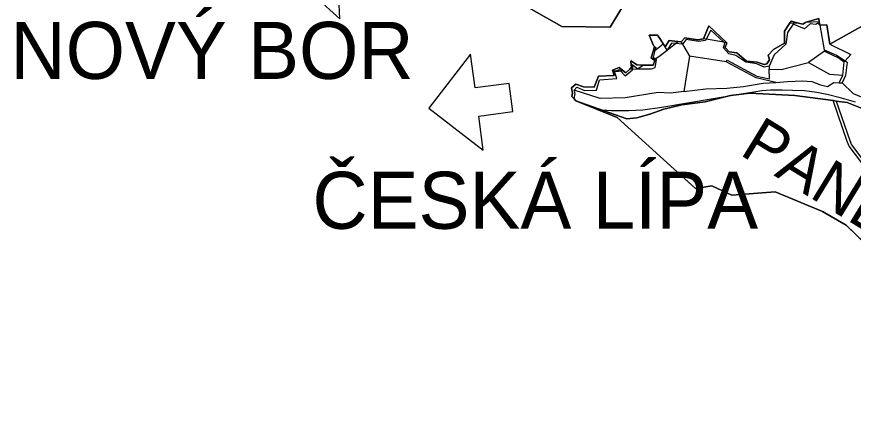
# Model space of a CAD drawing. Extents: x -706771 to -698463, y -971709 to -967107.
# Drawn here: x -706403 to -705305, y -970193 to -969665 of the extents above; entities that cross this region are included whole.
import ezdxf

# ---------------------------------------------------------------- set-up
doc = ezdxf.new("R2010")
doc.units = 0
for name, color, linetype in [('_KRAJINNY CELEK', 7, 'Continuous'), ('_KRAJINNY OKRSEK', 7, 'Continuous'), ('_KRAJINNY OKRSEK_popis', 7, 'Continuous'), ('Dráha_osa koleje', 7, 'Continuous'), ('Hranice katastralnich uzemi', 7, 'Continuous'), ('Hranice řešeného území', 7, 'Continuous'), ('KN_Hranice_parcel', 7, 'Continuous'), ('Komunikace popis smery a sipky', 7, 'Continuous'), ('Trasy cykloturistické N', 7, 'Continuous'), ('Typ krajiny běžné 5M2', 7, 'Continuous')]:
    doc.layers.add(name, color=color, linetype=linetype)

msp = doc.modelspace()

# ---------------------------------------------------------------- linework, layer by layer
at = {"layer": '_KRAJINNY CELEK'}
for points in [[(-705740.9, -969647.9), (-705687.4, -969678.2), (-705623.8, -969679), (-705593.1, -969627.6)], [(-705276.5, -969668.4), (-705335.3, -969701.6), (-705339.1, -969675.9), (-705348.7, -969676.4), (-705349.2, -969672.2), (-705349.9, -969667.5), (-705365, -969671.9), (-705367.1, -969673.1), (-705370.6, -969675.1), (-705376.6, -969673.6), (-705386.3, -969671.1), (-705388.2, -969674.3), (-705394.7, -969684.5), (-705394.9, -969700.3), (-705409.2, -969708.6), (-705416.3, -969715.9), (-705414.7, -969722.2), (-705418.1, -969727.2), (-705421.6, -969728.2), (-705430.7, -969725), (-705445, -969723.6), (-705457.7, -969712.8), (-705467.4, -969711.6), (-705473, -969705.6), (-705470.6, -969699.7), (-705494.1, -969677.1), (-705501.1, -969694.4), (-705508.8, -969695.8), (-705525.9, -969693.1), (-705530.6, -969698.3), (-705534.8, -969697.9), (-705546.5, -969696.7), (-705551.8, -969704.9), (-705554.2, -969701.1), (-705557.8, -969695.5), (-705561.6, -969689.6), (-705572.6, -969689.4), (-705566.9, -969703.3), (-705565.7, -969704.4), (-705567.4, -969711), (-705570, -969719.3), (-705566.7, -969722), (-705565.3, -969723.1), (-705567.2, -969729), (-705580.4, -969729.2), (-705588.9, -969728.7), (-705594.5, -969724.8), (-705596.7, -969723.2), (-705596.5, -969725.3), (-705595.9, -969731.7), (-705597.9, -969734.3), (-705603.4, -969739), (-705607.3, -969735.9), (-705612.2, -969732.1), (-705620.8, -969735.4), (-705620.2, -969737.1), (-705618.4, -969742.8), (-705639.1, -969743.7), (-705644.9, -969757.8), (-705658.9, -969757.7), (-705669.1, -969753.8), (-705674.6, -969758.8), (-705673.2, -969766), (-705674.2, -969770.1), (-705671.3, -969773.3), (-705669.1, -969775.8), (-705614.7, -969798), (-705511.8, -969891.3), (-705490.4, -969887.9), (-705463.9, -969899.8), (-705407.2, -969895.8), (-705344.8, -969921.3), (-705313.7, -969939.2), (-705269.7, -969982.5)]]:
    msp.add_lwpolyline(points, dxfattribs=at)
at = {"layer": '_KRAJINNY OKRSEK'}
for p, q in [((-705330.9, -969775.7), (-705381.4, -969769.1)), ((-705669.1, -969775.8), (-705614.7, -969798)), ((-705529.9, -969781.4), (-705553.4, -969786.8)), ((-705327.1, -969776.2), (-705330.9, -969775.7)), ((-705553.4, -969786.8), (-705571.6, -969793.4)), ((-705614.7, -969798), (-705511.8, -969891.3)), ((-705511.8, -969891.3), (-705490.4, -969887.9)), ((-705490.4, -969887.9), (-705463.9, -969899.8)), ((-705463.9, -969899.8), (-705407.2, -969895.8))]:
    msp.add_line(p, q, dxfattribs=at)
for points in [[(-705740.9, -969647.9), (-705687.4, -969678.2), (-705623.8, -969679), (-705593.1, -969627.6)], [(-705276.5, -969668.4), (-705335.3, -969701.6), (-705339.1, -969675.9), (-705348.7, -969676.4), (-705349.2, -969672.2), (-705349.9, -969667.5), (-705365, -969671.9), (-705367.1, -969673.1), (-705370.6, -969675.1), (-705376.6, -969673.6), (-705386.3, -969671.1), (-705388.2, -969674.3), (-705394.7, -969684.5), (-705394.9, -969700.3), (-705409.2, -969708.6), (-705416.3, -969715.9), (-705414.7, -969722.2), (-705418.1, -969727.2), (-705421.6, -969728.2), (-705430.7, -969725), (-705445, -969723.6), (-705457.7, -969712.8), (-705467.4, -969711.6), (-705473, -969705.6), (-705470.6, -969699.7), (-705494.1, -969677.1), (-705501.1, -969694.4), (-705508.8, -969695.8), (-705525.9, -969693.1), (-705530.6, -969698.3), (-705534.8, -969697.9), (-705546.5, -969696.7), (-705551.8, -969704.9), (-705554.2, -969701.1), (-705557.8, -969695.5), (-705561.6, -969689.6), (-705572.6, -969689.4), (-705566.9, -969703.3), (-705565.7, -969704.4), (-705567.4, -969711), (-705570, -969719.3), (-705566.7, -969722), (-705565.3, -969723.1), (-705567.2, -969729), (-705580.4, -969729.2), (-705588.9, -969728.7), (-705594.5, -969724.8), (-705596.7, -969723.2), (-705596.5, -969725.3), (-705595.9, -969731.7), (-705597.9, -969734.3), (-705603.4, -969739), (-705607.3, -969735.9), (-705612.2, -969732.1), (-705620.8, -969735.4), (-705620.2, -969737.1), (-705618.4, -969742.8), (-705639.1, -969743.7), (-705644.9, -969757.8), (-705658.9, -969757.7), (-705669.1, -969753.8), (-705674.6, -969758.8), (-705673.2, -969766), (-705674.2, -969770.1), (-705671.3, -969773.3), (-705669.1, -969775.8)], [(-705669.1, -969775.8), (-705601.9, -969799.5), (-705589, -969798.2), (-705571.6, -969793.4), (-705553.4, -969786.8), (-705529.9, -969781.4), (-705499, -969777.4), (-705465.6, -969768.8), (-705440.5, -969765.8), (-705381.4, -969769.1), (-705330.9, -969775.7), (-705327.1, -969776.2), (-705312.8, -969778.1), (-705282, -969790.5), (-705271.3, -969796.9), (-705242.7, -969817), (-705218.4, -969838.2), (-705184.7, -969864.5), (-705155.9, -969891.9), (-705141.2, -969879.4), (-705133, -969887.2), (-705116.4, -969899)], [(-705381.4, -969769.1), (-705440.5, -969765.8), (-705465.6, -969768.8), (-705499, -969777.4), (-705529.9, -969781.4)], [(-705571.6, -969793.4), (-705589, -969798.2), (-705601.9, -969799.5), (-705669.1, -969775.8)], [(-705282, -969790.5), (-705312.8, -969778.1), (-705327.1, -969776.2)], [(-705407.2, -969895.8), (-705344.8, -969921.3), (-705313.7, -969939.2), (-705269.7, -969982.5), (-705267.9, -969984.3)]]:
    msp.add_lwpolyline(points, dxfattribs=at)
at = {"layer": 'Dráha_osa koleje'}
msp.add_lwpolyline([(-705640.4, -969787.5), (-705622.1, -969788.5), (-705599.1, -969788.8), (-705581.1, -969787.8), (-705556.2, -969784.4), (-705454.7, -969767.2), (-705438, -969764.6), (-705424.6, -969762.5), (-705413.3, -969761.6), (-705397.8, -969761.4), (-705384.6, -969761.8), (-705368.8, -969762.5), (-705352.4, -969764.5), (-705337.2, -969767.4), (-705323.4, -969771.2), (-705302.1, -969777.4)], dxfattribs=at)
at = {"layer": 'Hranice katastralnich uzemi'}
for points in [[(-705740.9, -969647.9), (-705687.4, -969678.2), (-705623.8, -969679), (-705593.1, -969627.6)], [(-705276.5, -969668.4), (-705335.3, -969701.6), (-705339.1, -969675.9), (-705348.7, -969676.4), (-705349.2, -969672.2), (-705349.9, -969667.5), (-705365, -969671.9), (-705367.1, -969673.1), (-705370.6, -969675.1), (-705376.6, -969673.6), (-705386.3, -969671.1), (-705388.2, -969674.3), (-705394.7, -969684.5), (-705394.9, -969700.3), (-705409.2, -969708.6), (-705416.3, -969715.9), (-705414.7, -969722.2), (-705418.1, -969727.2), (-705421.6, -969728.2), (-705430.7, -969725), (-705445, -969723.6), (-705457.7, -969712.8), (-705467.4, -969711.6), (-705473, -969705.6), (-705470.6, -969699.7), (-705494.1, -969677.1), (-705501.1, -969694.4), (-705508.8, -969695.8), (-705525.9, -969693.1), (-705530.6, -969698.3), (-705534.8, -969697.9), (-705546.5, -969696.7), (-705551.8, -969704.9), (-705554.2, -969701.1), (-705557.8, -969695.5)], [(-705557.8, -969695.5), (-705561.6, -969689.6), (-705572.6, -969689.4), (-705566.9, -969703.3), (-705565.7, -969704.4), (-705567.4, -969711), (-705570, -969719.3), (-705566.7, -969722), (-705565.3, -969723.1), (-705567.2, -969729), (-705580.4, -969729.2), (-705588.9, -969728.7), (-705594.5, -969724.8), (-705596.7, -969723.2), (-705596.5, -969725.3), (-705595.9, -969731.7), (-705597.9, -969734.3), (-705603.4, -969739), (-705607.3, -969735.9), (-705612.2, -969732.1), (-705620.8, -969735.4), (-705620.2, -969737.1), (-705618.4, -969742.8), (-705639.1, -969743.7), (-705644.9, -969757.8), (-705658.9, -969757.7), (-705669.1, -969753.8), (-705674.6, -969758.8), (-705673.2, -969766), (-705674.2, -969770.1), (-705671.3, -969773.3), (-705669.1, -969775.8), (-705614.7, -969798), (-705511.8, -969891.3), (-705490.4, -969887.9), (-705463.9, -969899.8), (-705407.2, -969895.8), (-705344.8, -969921.3), (-705313.7, -969939.2), (-705269.7, -969982.5)]]:
    msp.add_lwpolyline(points, dxfattribs=at)
at = {"layer": 'Hranice řešeného území'}
for points in [[(-705593.1, -969627.6), (-705623.8, -969679), (-705687.4, -969678.2), (-705740.9, -969647.9)], [(-705269.7, -969982.5), (-705313.7, -969939.2), (-705344.8, -969921.3), (-705407.2, -969895.8), (-705463.9, -969899.8), (-705490.4, -969887.9), (-705511.8, -969891.3), (-705614.7, -969798), (-705669.1, -969775.8), (-705671.3, -969773.3), (-705674.2, -969770.1), (-705673.2, -969766), (-705674.6, -969758.8), (-705669.1, -969753.8), (-705658.9, -969757.7), (-705644.9, -969757.8), (-705639.1, -969743.7), (-705618.4, -969742.8), (-705620.2, -969737.1), (-705620.8, -969735.4), (-705612.2, -969732.1), (-705607.3, -969735.9), (-705603.4, -969739), (-705597.9, -969734.3), (-705595.9, -969731.7), (-705596.5, -969725.3), (-705596.7, -969723.2), (-705594.5, -969724.8), (-705588.9, -969728.7), (-705580.4, -969729.2), (-705567.2, -969729), (-705565.3, -969723.1), (-705566.7, -969722), (-705570, -969719.3), (-705567.4, -969711), (-705565.7, -969704.4), (-705566.9, -969703.3), (-705572.6, -969689.4), (-705561.6, -969689.6), (-705557.8, -969695.5), (-705554.2, -969701.1), (-705551.8, -969704.9), (-705546.5, -969696.7), (-705534.8, -969697.9), (-705530.6, -969698.3), (-705525.9, -969693.1), (-705508.8, -969695.8), (-705501.1, -969694.4), (-705494.1, -969677.1), (-705470.6, -969699.7), (-705473, -969705.6), (-705467.4, -969711.6), (-705457.7, -969712.8), (-705445, -969723.6), (-705430.7, -969725), (-705421.6, -969728.2), (-705418.1, -969727.2), (-705414.7, -969722.2), (-705416.3, -969715.9), (-705409.2, -969708.6), (-705394.9, -969700.3), (-705394.7, -969684.5), (-705388.2, -969674.3), (-705386.3, -969671.1), (-705376.6, -969673.6), (-705370.6, -969675.1), (-705367.1, -969673.1), (-705365, -969671.9), (-705349.9, -969667.5), (-705349.2, -969672.2), (-705348.7, -969676.4), (-705339.1, -969675.9), (-705335.3, -969701.6), (-705276.5, -969668.4)]]:
    msp.add_lwpolyline(points, dxfattribs=at)
at = {"layer": 'KN_Hranice_parcel'}
for p, q in [((-705376.6, -969673.6), (-705388.2, -969674.3)), ((-705349.2, -969672.2), (-705367.1, -969673.1)), ((-705348.7, -969676.4), (-705349.2, -969672.2)), ((-705276.5, -969668.4), (-705335.3, -969701.6)), ((-705494.1, -969677.1), (-705501.1, -969694.4)), ((-705470.6, -969699.7), (-705494.1, -969677.1)), ((-705348.7, -969676.4), (-705342.6, -969709)), ((-705554.2, -969701.1), (-705557.8, -969695.5)), ((-705497.8, -969694.9), (-705501.1, -969694.4)), ((-705474.7, -969699), (-705497.8, -969694.9)), ((-705565.7, -969704.4), (-705567.4, -969711)), ((-705566.9, -969703.3), (-705565.7, -969704.4)), ((-705565.1, -969709.7), (-705554.2, -969701.1)), ((-705551.8, -969704.9), (-705554.2, -969701.1)), ((-705549, -969709.2), (-705551.8, -969704.9)), ((-705549, -969709.2), (-705538, -969700.5)), ((-705538, -969700.5), (-705534.8, -969697.9)), ((-705528.8, -969701.4), (-705538, -969700.5)), ((-705530.6, -969698.3), (-705534.8, -969697.9)), ((-705528.8, -969701.4), (-705530.6, -969698.3)), ((-705528.8, -969701.4), (-705519.7, -969717.2)), ((-705470.6, -969699.7), (-705474.7, -969699)), ((-705393.1, -969701.3), (-705394.9, -969700.3)), ((-705565.1, -969709.7), (-705567.4, -969711)), ((-705519.7, -969717.2), (-705527.2, -969763.5)), ((-705471.5, -969724.7), (-705519.7, -969717.2)), ((-705342.2, -969710.8), (-705363.2, -969725.5)), ((-705342.6, -969709), (-705342.2, -969710.8)), ((-705594.5, -969724.8), (-705596.5, -969725.3)), ((-705588.1, -969733.7), (-705580.4, -969729.2)), ((-705564.7, -969720.8), (-705566.7, -969722)), ((-705318.5, -969742.3), (-705316.4, -969724.8)), ((-705316.4, -969724.8), (-705315.2, -969723.4)), ((-705616.8, -969736.9), (-705620.2, -969737.1)), ((-705610.4, -969736.4), (-705607.3, -969735.9)), ((-705594.7, -969734.1), (-705597.9, -969734.3)), ((-705594.7, -969734.1), (-705588.1, -969733.7)), ((-705415, -969730.3), (-705415, -969734.2)), ((-705323.3, -969752.3), (-705318.5, -969742.3)), ((-705323.3, -969752.3), (-705319.1, -969752.4)), ((-705671.3, -969773.3), (-705669.1, -969775.8)), ((-705669.1, -969775.8), (-705614.7, -969798)), ((-705327.1, -969776.2), (-705330.9, -969775.7)), ((-705313.7, -969939.2), (-705269.7, -969982.5))]:
    msp.add_line(p, q, dxfattribs=at)
for points in [[(-705740.9, -969647.9), (-705687.4, -969678.2), (-705623.8, -969679), (-705593.1, -969627.6)], [(-705388.2, -969674.3), (-705394.7, -969684.5), (-705394.9, -969700.3)], [(-705348.7, -969676.4), (-705351.3, -969673.9), (-705353.9, -969675.6), (-705361.4, -969674.8), (-705368.5, -969681.2), (-705383.6, -969675), (-705390.8, -969686.2), (-705393.1, -969701.3)], [(-705376.6, -969673.6), (-705386.3, -969671.1), (-705388.2, -969674.3)], [(-705367.1, -969673.1), (-705370.6, -969675.1), (-705376.6, -969673.6)], [(-705349.2, -969672.2), (-705349.9, -969667.5), (-705365, -969671.9), (-705367.1, -969673.1)], [(-705474.7, -969699), (-705491.8, -969683.2), (-705497.8, -969694.9)], [(-705335.3, -969701.6), (-705339.1, -969675.9), (-705348.7, -969676.4)], [(-705557.8, -969695.5), (-705561.6, -969689.6), (-705572.6, -969689.4), (-705566.9, -969703.3)], [(-705501.1, -969694.4), (-705508.8, -969695.8), (-705525.9, -969693.1), (-705530.6, -969698.3)], [(-705497.8, -969694.9), (-705498.6, -969696.6), (-705507.9, -969697.7), (-705524, -969695.1), (-705528.8, -969701.4)], [(-705565.7, -969704.4), (-705564, -969705.8), (-705565.1, -969709.7)], [(-705534.8, -969697.9), (-705546.5, -969696.7), (-705551.8, -969704.9)], [(-705538, -969700.5), (-705543.5, -969699.9), (-705549, -969709.2)], [(-705415, -969730.3), (-705421.5, -969731.5), (-705431.2, -969727.2), (-705445.6, -969725.3), (-705458.8, -969716.2), (-705467.8, -969714.3), (-705475.1, -969706.4), (-705473.2, -969700.3), (-705474.7, -969699)], [(-705394.9, -969700.3), (-705409.2, -969708.6), (-705416.3, -969715.9), (-705414.7, -969722.2), (-705418.1, -969727.2), (-705421.6, -969728.2), (-705430.7, -969725), (-705445, -969723.6), (-705457.7, -969712.8), (-705467.4, -969711.6), (-705473, -969705.6), (-705470.6, -969699.7)], [(-705393.1, -969701.3), (-705408.6, -969715.4), (-705415, -969730.3)], [(-705335.3, -969701.6), (-705308, -969714.8), (-705315.2, -969723.4)], [(-705567.4, -969711), (-705570, -969719.3), (-705566.7, -969722)], [(-705565.1, -969709.7), (-705567.5, -969718.4), (-705564.7, -969720.8)], [(-705564.7, -969720.8), (-705560, -969717.8), (-705549, -969709.2)], [(-705342.6, -969709), (-705326.6, -969716), (-705315.2, -969723.4)], [(-705342.2, -969710.8), (-705323.3, -969720), (-705316.4, -969724.8)], [(-705596.5, -969725.3), (-705595.9, -969731.7), (-705597.9, -969734.3)], [(-705594.5, -969724.8), (-705596.7, -969723.2), (-705596.5, -969725.3)], [(-705588.1, -969733.7), (-705595, -969728.4), (-705594.7, -969731.6), (-705594.7, -969734.1)], [(-705580.4, -969729.2), (-705588.9, -969728.7), (-705594.5, -969724.8)], [(-705588.1, -969733.7), (-705580.8, -969733.9), (-705569.4, -969733.8), (-705564.7, -969732), (-705563.1, -969722.2), (-705564.7, -969720.8)], [(-705566.7, -969722), (-705565.3, -969723.1), (-705567.2, -969729), (-705580.4, -969729.2)], [(-705471.5, -969724.7), (-705470.2, -969722.3), (-705431.1, -969743.5), (-705414.7, -969747.1), (-705415, -969734.2)], [(-705406.3, -969751.7), (-705431.9, -969745.5), (-705471.5, -969724.7)], [(-705415, -969734.2), (-705399.2, -969734.9), (-705363.2, -969725.5)], [(-705363.2, -969725.5), (-705335.8, -969741), (-705318.5, -969742.3)], [(-705315.2, -969723.4), (-705312.8, -969724.9), (-705314.7, -969742.8), (-705319.1, -969752.4)], [(-705620.2, -969737.1), (-705618.4, -969742.8), (-705639.1, -969743.7), (-705644.9, -969757.8), (-705658.9, -969757.7), (-705669.1, -969753.8), (-705674.6, -969758.8), (-705673.2, -969766), (-705674.2, -969770.1), (-705671.3, -969773.3)], [(-705671.3, -969761.8), (-705667.6, -969758.1), (-705657.7, -969762.2), (-705641.8, -969761.9), (-705637.8, -969748.3), (-705615.2, -969746.7), (-705618.3, -969737.5), (-705616.8, -969736.9)], [(-705607.3, -969735.9), (-705612.2, -969732.1), (-705620.8, -969735.4), (-705620.2, -969737.1)], [(-705610.4, -969736.4), (-705611.7, -969735.1), (-705616.8, -969736.9)], [(-705616.8, -969736.9), (-705612.8, -969736.8), (-705610.4, -969736.4)], [(-705610.4, -969736.4), (-705604, -969743.2), (-705594.6, -969735.3), (-705594.7, -969734.1)], [(-705597.9, -969734.3), (-705603.4, -969739), (-705607.3, -969735.9)], [(-705406.3, -969751.7), (-705391.1, -969750.6), (-705370.9, -969749.8), (-705358.8, -969750.7), (-705347.6, -969754.9), (-705338.6, -969756.9), (-705330.2, -969752), (-705323.3, -969752.3)], [(-705671.3, -969773.3), (-705670, -969766.2), (-705671.3, -969761.8)], [(-705527.2, -969763.5), (-705544.8, -969765.8), (-705560.6, -969764.8), (-705604.1, -969772.1), (-705636.8, -969772.8), (-705671.3, -969761.8)], [(-705527.2, -969763.5), (-705498, -969760.2), (-705470.7, -969759.3), (-705448.9, -969756.9), (-705423.1, -969752.5), (-705406.3, -969751.7)], [(-705319.1, -969752.4), (-705304.6, -969766.2), (-705285.8, -969774), (-705252.7, -969790.4), (-705205.4, -969818.8)], [(-705330.9, -969775.7), (-705381.4, -969769.1), (-705440.5, -969765.8), (-705465.6, -969768.8), (-705499, -969777.4), (-705529.9, -969781.4), (-705553.4, -969786.8), (-705562.7, -969790.4), (-705571.6, -969793.4), (-705589, -969798.2), (-705601.9, -969799.5), (-705669.1, -969775.8)], [(-705269.7, -969982.5), (-705270.7, -969952.9), (-705260.1, -969931.2), (-705259.6, -969906.6), (-705275.6, -969881), (-705310.1, -969835.6), (-705312.5, -969829.6), (-705330.9, -969775.7)], [(-705116.4, -969899), (-705133, -969887.2), (-705141.2, -969879.4), (-705155.9, -969891.9), (-705184.7, -969864.5), (-705218.4, -969838.2), (-705242.7, -969817), (-705271.3, -969796.9), (-705282, -969790.5), (-705312.8, -969778.1), (-705327.1, -969776.2)], [(-705327.1, -969776.2), (-705309.3, -969828.1), (-705306.8, -969833.9), (-705268.7, -969884.3), (-705255.4, -969904.4), (-705255.6, -969933.8), (-705265.9, -969955.8), (-705263.8, -969987.6)], [(-705614.7, -969798), (-705511.8, -969891.3), (-705490.4, -969887.9), (-705463.9, -969899.8), (-705407.2, -969895.8), (-705344.8, -969921.3), (-705313.7, -969939.2)]]:
    msp.add_lwpolyline(points, dxfattribs=at)
at = {"layer": 'Komunikace popis smery a sipky'}
for p, q in [((-706045.4, -969607.6), (-705978.9, -969668.2)), ((-705978.9, -969668.2), (-705981, -969623.2)), ((-705807.1, -969714.4), (-705861.9, -969785.7)), ((-705801.2, -969759), (-705807.1, -969714.4)), ((-705756.6, -969753.1), (-705801.2, -969759)), ((-705751.8, -969790.1), (-705756.6, -969753.1)), ((-705861.9, -969785.7), (-705790.6, -969840.6)), ((-705796.4, -969795.9), (-705751.8, -969790.1)), ((-705790.6, -969840.6), (-705796.4, -969795.9))]:
    msp.add_line(p, q, dxfattribs=at)
at = {"layer": 'Trasy cykloturistické N'}
msp.add_lwpolyline([(-705567.4, -969711), (-705565.1, -969709.7), (-705554.2, -969701.1)], dxfattribs=at)
at = {"layer": 'Typ krajiny běžné 5M2'}
for points in [[(-705740.9, -969647.9), (-705687.4, -969678.2), (-705623.8, -969679), (-705593.1, -969627.6)], [(-705276.5, -969668.4), (-705335.3, -969701.6), (-705339.1, -969675.9), (-705348.7, -969676.4), (-705349.2, -969672.2), (-705349.9, -969667.5), (-705365, -969671.9), (-705367.1, -969673.1), (-705370.6, -969675.1), (-705376.6, -969673.6), (-705386.3, -969671.1), (-705388.2, -969674.3), (-705394.7, -969684.5), (-705394.9, -969700.3), (-705409.2, -969708.6), (-705416.3, -969715.9), (-705414.7, -969722.2), (-705418.1, -969727.2), (-705421.6, -969728.2), (-705430.7, -969725), (-705445, -969723.6), (-705457.7, -969712.8), (-705467.4, -969711.6), (-705473, -969705.6), (-705470.6, -969699.7), (-705494.1, -969677.1), (-705501.1, -969694.4), (-705508.8, -969695.8), (-705525.9, -969693.1), (-705530.6, -969698.3), (-705534.8, -969697.9), (-705546.5, -969696.7), (-705551.8, -969704.9), (-705554.2, -969701.1), (-705557.8, -969695.5), (-705561.6, -969689.6), (-705572.6, -969689.4), (-705566.9, -969703.3), (-705565.7, -969704.4), (-705567.4, -969711), (-705570, -969719.3), (-705566.7, -969722), (-705565.3, -969723.1), (-705567.2, -969729), (-705580.4, -969729.2), (-705588.9, -969728.7), (-705594.5, -969724.8), (-705596.7, -969723.2), (-705596.5, -969725.3), (-705595.9, -969731.7), (-705597.9, -969734.3), (-705603.4, -969739), (-705607.3, -969735.9), (-705612.2, -969732.1), (-705620.8, -969735.4), (-705620.2, -969737.1), (-705618.4, -969742.8), (-705639.1, -969743.7), (-705644.9, -969757.8), (-705658.9, -969757.7), (-705669.1, -969753.8), (-705674.6, -969758.8), (-705673.2, -969766), (-705674.2, -969770.1), (-705671.3, -969773.3), (-705669.1, -969775.8), (-705614.7, -969798), (-705511.8, -969891.3), (-705490.4, -969887.9), (-705463.9, -969899.8), (-705407.2, -969895.8), (-705344.8, -969921.3), (-705313.7, -969939.2), (-705269.7, -969982.5)]]:
    msp.add_lwpolyline(points, dxfattribs=at)

# ---------------------------------------------------------------- texts
at = {"layer": '_KRAJINNY OKRSEK_popis'}
msp.add_text('PANENSKÁ STRÁŇ', height=60, rotation=328.5977, dxfattribs=at).set_placement((-705455.3, -969845.9))
at = {"layer": 'Komunikace popis smery a sipky'}
for s, p in [('NOVÝ BOR', (-706411.4, -969747.1)), ('ČESKÁ LÍPA', (-706014.8, -969944.2))]:
    msp.add_text(s, height=75, dxfattribs=at).set_placement(p)

doc.saveas('drawing.dxf')
